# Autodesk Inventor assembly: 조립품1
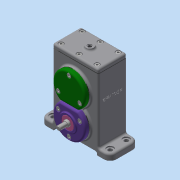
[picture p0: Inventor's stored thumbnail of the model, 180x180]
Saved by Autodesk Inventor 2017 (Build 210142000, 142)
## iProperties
Part Number: 조립품1
Material: 일반
Document SubType Name: Assembly
Designer: mrc
Author: mrc
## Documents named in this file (24)
- C:\Users\mrc\Desktop\600506V1051\조립품1.iam
- C:\Users\mrc\Desktop\600506V1051\본체.ipt
- C:\Users\mrc\Desktop\600506V1051\개스킷 A.ipt
- C:\Users\mrc\Desktop\600506V1051\개스킷 B.ipt
- C:\Users\mrc\Desktop\600506V1051\개스킷 C.ipt
- C:\Users\mrc\Desktop\600506V1051\베어링 6001.ipt
- 베어링 6001.ipt
- C:\Users\mrc\Desktop\600506V1051\베어링 6002.ipt
- 베어링 6002.ipt
- C:\Users\mrc\Desktop\600506V1051\볼트 M4.ipt
- C:\Users\mrc\Desktop\600506V1051\스퍼기어 A.ipt
- C:\Users\mrc\Desktop\600506V1051\스퍼기어 B.ipt
- C:\Users\mrc\Desktop\600506V1051\오일 실 10 20 7.ipt
- C:\Users\mrc\Desktop\600506V1051\오일 실 12 22 7.ipt
- C:\Users\mrc\Desktop\600506V1051\축 A.ipt
- C:\Users\mrc\Desktop\600506V1051\축 B.ipt
- C:\Users\mrc\Desktop\600506V1051\칼라.ipt
- C:\Users\mrc\Desktop\600506V1051\커버 A.ipt
- C:\Users\mrc\Desktop\600506V1051\커버 B.ipt
- C:\Users\mrc\Desktop\600506V1051\커버 C.ipt
- C:\Users\mrc\Desktop\600506V1051\커버 E.ipt
- C:\Users\mrc\Desktop\600506V1051\키 4 x 4 x 12.ipt
- C:\Users\mrc\Desktop\600506V1051\키 5 x 5 x 12.ipt
- C:\Users\mrc\Desktop\600506V1051\커버 D.ipt
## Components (5 placed, 3 different names)
1. 개스킷 A:1
2. 개스킷 B:1
3. 개스킷 C:1
4. 개스킷 B:2
5. 개스킷 B:3
